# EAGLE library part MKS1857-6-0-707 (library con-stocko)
Serie MKS 1850 Lötstifte In-line, Raster 2.5 mm, Stiftwannen, stehend, mit Rastlasche Source: http://www.stocko.de/de/index.php?seite=ka_rfk2_mks1850.html&rubrik=Katalog+-+RFK+2 rfk_1850.pdf
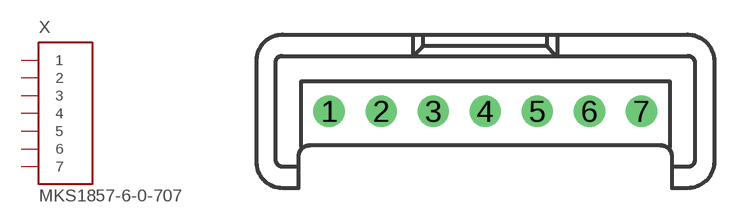
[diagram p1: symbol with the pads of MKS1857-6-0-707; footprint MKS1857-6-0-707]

Designator prefix X

## MKS1857-6-0-707 (OC_FARNELL: unknown; OC_NEWARK: unknown)  [MKS1857-6-0-707]
1  1  in
2  2  in
3  3  in
4  4  in
5  5  in
6  6  in
7  7  in

## Footprint MKS1857-6-0-707 (pad centres in mm)
Serie MKS 1850 Lötstifte In-line, Raster 2.5 mm, Stiftwannen, stehend, mit Rastlasche Source: http://www.stocko.de/de/index.php?seite=ka_rfk2_mks1850.html&rubrik=Katalog+-+RFK+2 rfk_1850.pdf
drill 1 pad 1.422 round: 1 -7.5,0; 2 -5,0; 3 -2.5,0; 4 0,0; 5 2.5,0; 6 5,0; 7 7.5,0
